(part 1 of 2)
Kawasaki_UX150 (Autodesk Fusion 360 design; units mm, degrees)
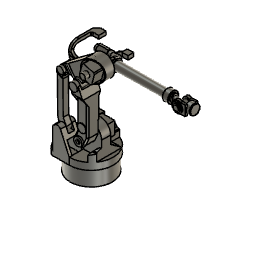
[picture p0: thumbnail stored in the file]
sketch "Esquisse1" plane through (0, 0, 0) normal (0, 0, 1) x axis (1, 0, 0)
sketch "Esquisse2" plane through (0, 0, 0) normal (0, 1, 0) x axis (1, 0, 0)
  line L1 (0, -3220) -> (0, 0)
  line L2 (335, -3220) -> (0, -3220)
  line L3 (2531, -3220) -> (335, -3220)
  line L4 (-1080, 0) -> (0, 0)
  point P1 (0, 0)
  point P2 (0, 0)
  point P6 (0, 0)
  point P3 (0, -3220)
  point P4 (335, -3220)
  point P5 (2531, -3220)
  point P7 (-1080, 0)
  coincident P1 P2
  perpendicular L1 L2
  perpendicular L1 L3
  coincident P1 P6
  dimension "d6" distance P2 P3 = 3220
  dimension "d7" distance P3 P4 = 335
  dimension "d8" distance P4 P5 = 2196
  dimension "d10" distance P6 P7 = 1080
canvas "Zone de dessin1"
sketch "Esquisse3" plane through (0, 0, 0) normal (0, 1, 0) x axis (1, 0, 0)
  line L1 (535, 0) -> (0, 0)
  line L2 (535, -700) -> (535, 0)
  line L3 (0, -700) -> (535, -700)
  line L4 (0, 0) -> (0, -700)
  line L5 (0, -3220) -> (0, 0)
  line L6 (335, -3220) -> (0, -3220)
  line L7 (335, -1870) -> (335, -3220)
  line L8 (335, -1600) -> (335, -1870)
  line L9 (135, -1600) -> (335, -1600)
  line L10 (135, -700) -> (135, -1600)
  line L11 (335, -3425) -> (335, -3220)
  line L12 (335, -3020) -> (335, -3220)
  line L13 (400, 0) -> (0, 0)
  line L14 (400, -400) -> (400, 0)
  line L15 (0, -400) -> (400, -400)
  line L16 (0, 0) -> (0, -400)
  line L17 (380, 0) -> (0, 0)
  line L18 (380, -275) -> (380, 0)
  line L19 (0, -275) -> (380, -275)
  line L20 (0, 0) -> (0, -275)
  line L21 (400, -275) -> (380, -275)
  line L22 (327.5, -400) -> (327.5, -700)
  line L23 (-215, -400) -> (0, -400)
  line L24 (-215, -735) -> (-215, -400)
  line L25 (-157.7529, -760.0802) -> (0, -400)
  line L26 (-465, -400) -> (0, -400)
  line L27 (-300, -400) -> (-465, -400)
  line L28 (-300, -750) -> (-300, -400)
  line L29 (-252.0768, -785.3146) -> (-300, -750)
  line L30 (-465, -400) -> (-300, -750)
  line L31 (-215, -1635) -> (-215, -735)
  line L32 (-215, -875) -> (-215, -735)
  line L33 (-215, -1475) -> (-215, -1635)
  line L34 (-159.3785, -1612.5) -> (-215, -1475)
  line L35 (-157.7529, -760.0802) -> (-215, -875)
  line L36 (-315, -1475) -> (-215, -1475)
  line L37 (-315, -850) -> (-315, -1475)
  line L38 (-274.8333, -716.9384) -> (-315, -850)
  line L39 (-315, -1520) -> (-315, -1475)
  line L40 (-272.1202, -1653.3654) -> (-315, -1520)
  line L41 (-159.3785, -1612.5) -> (135, -1600)
  line L42 (200, -1679) -> (335, -1679)
  line L43 (200, -1637.4166) -> (200, -1679)
  line L44 (223.3067, -2024.9374) -> (-250.0869, -1683.6714)
  circle C1 centre (335, -1870) radius 191
  circle C2 centre (335, -3220) radius 100
  circle C3 centre (135, -700) radius 192.5
  circle C4 centre (-215, -735) radius 62.5
  circle C5 centre (-215, -1635) radius 60
  circle C6 centre (135, -1600) radius 75
  point P1 (0, 0)
  point P2 (0, 0)
  point P6 (0, 0)
  point P7 (0, 0)
  point P13 (135, -700)
  point P10 (335, -1870)
  point P14 (335, -1870)
  point P9 (335, -3220)
  point P15 (335, -3220)
  point P16 (335, -3220)
  point P18 (335, -3020)
  point P19 (135, -700)
  point P23 (0, 0)
  point P27 (400, -275)
  point P28 (327.5, -700)
  point P29 (327.5, -400)
  point P31 (-215, -735)
  point P32 (-215, -735)
  point P33 (-157.7529, -760.0802)
  point P35 (-300, -400)
  point P37 (-252.0768, -785.3146)
  point P38 (-215, -1635)
  point P39 (-215, -1635)
  point P40 (-215, -875)
  point P41 (-215, -1475)
  point P42 (-159.3785, -1612.5)
  point P45 (-274.8333, -716.9384)
  point P47 (-272.1202, -1653.3654)
  point P12 (135, -1600)
  point P48 (135, -1600)
  point P49 (335, -1679)
  point P51 (200, -1637.4166)
  point P52 (-250.0869, -1683.6714)
  point P53 (223.3067, -2024.9374)
  point P3 (535, 0)
  point P8 (0, -3220)
  point P11 (335, -1600)
  point P17 (335, -3425)
  point P20 (400, 0)
  point P22 (0, -400)
  point P24 (380, 0)
  point P30 (-215, -400)
  point P34 (-465, -400)
  point P43 (-315, -1475)
  coincident P1 P2
  horizontal L1
  perpendicular L1 L2
  perpendicular L2 L3
  coincident P1 P6
  perpendicular L1 L4
  coincident P1 P7
  perpendicular L1 L5
  perpendicular L4 L6
  perpendicular L6 L7
  perpendicular L6 L8
  perpendicular L8 L9
  coincident L3 P13
  perpendicular L3 L10
  coincident P10 P14
  coincident P9 P15
  coincident P15 P16
  perpendicular L6 L11
  coincident L7 P18
  coincident P13 P19
  horizontal L13
  vertical L14
  horizontal L15
  vertical L16
  horizontal L17
  vertical L18
  horizontal L19
  vertical L20
  coincident P1 P23
  coincident L14 P27
  perpendicular L14 L21
  coincident C3 P28
  coincident L3 P28
  coincident L15 P29
  tangent C3 L22
  perpendicular L5 L23
  perpendicular L23 L24
  coincident P31 P32
  coincident C4 P33
  tangent C4 L25
  perpendicular L24 L26
  coincident L26 P35
  perpendicular L24 L27
  perpendicular L26 L28
  coincident C4 P37
  tangent C4 L29
  parallel L24 L31
  coincident P38 P39
  coincident L31 P40
  coincident L31 P41
  coincident C5 P42
  tangent C5 L34
  perpendicular L33 L36
  perpendicular L36 L37
  coincident C4 P45
  tangent C4 L38
  perpendicular L36 L39
  coincident C5 P47
  tangent C5 L40
  coincident P12 P48
  coincident C1 P49
  coincident L8 P49
  tangent C1 L42
  coincident C6 P51
  perpendicular L9 L43
  coincident C5 P52
  tangent C5 L44
  coincident C1 P53
  tangent C1 L44
  dimension "d11" distance P2 P3 = 535
  dimension "d12" distance P7 P8 = 3220
  dimension "d13" distance P8 P9 = 335
  dimension "d14" distance P9 P10 = 1350
  dimension "d15" distance P10 P11 = 270
  dimension "d16" distance P11 P12 = 200
  dimension "d17" diameter C1 = 382 (= "( 191 * 2 ) * 1 mm")
  dimension "d18" diameter C2 = 200
  dimension "d19" distance P16 P17 = 205
  dimension "d20" distance P9 P18 = 200
  dimension "d21" diameter C3 = 385
  dimension "d22" distance P6 P20 = 400
  dimension "d23" distance P6 P22 = 400
  dimension "d24" distance P23 P24 = 380
  dimension "d28" distance P22 P30 = 215
  dimension "d29" distance P30 P31 = 335
  dimension "d30" diameter C4 = 125
  dimension "d31" distance P22 P34 = 465
  dimension "d101" distance P31 P38 = 900
  dimension "d102" diameter C5 = 120
  dimension "d103" distance P41 P43 = 100
  dimension "d118" diameter C6 = 150
revolve "Révolution1" sketch "Esquisse3" AlongAngle 360
sketch "Esquisse4" plane through (0, 0, 0) normal (1, 0, 0) x axis (0, 1, 0)
  line L1 (0, 3425) -> (0, 0)
  point P1 (0, 0)
  point P2 (0, 0)
  point P3 (0, 3425)
  coincident P1 P2
  vertical L1
  dimension "d26" distance P2 P3 = 3425 (= "700 mm + 900 mm + 270 mm + 1350 mm + 205 mm")
revolve "Révolution3" sketch "Esquisse3" AlongAngle 360
canvas "Zone de dessin2"
revolve "Révolution2" sketch "Esquisse3" AlongAngle 360
extrude "Extrusion1" add sketch "Esquisse3" profile of L23 L24 C4 L25 L26 L27 L28 L29 L30 against normal blind 400
extrude "Extrusion2" cut of existing geometry blind -300
sketch "Esquisse5" plane through (0, 0, 0) normal (1, 0, 0) x axis (0, 1, 0)
  line L1 (0, 700) -> (0, 0)
  line L2 (25, 700) -> (0, 700)
  line L3 (25, 885) -> (25, 700)
  line L4 (-140, 885) -> (25, 885)
  line L5 (-140, 400) -> (-140, 885)
  line L6 (0, 400) -> (-140, 400)
  line L7 (25, 885) -> (-140, 885)
  line L8 (25, 400) -> (25, 885)
  line L9 (-140, 400) -> (25, 400)
  line L10 (-140, 885) -> (-140, 400)
  point P1 (0, 0)
  point P2 (0, 0)
  point P8 (0, 400)
  point P4 (25, 700)
  point P5 (25, 885)
  point P6 (-140, 885)
  coincident P1 P2
  vertical L1
  perpendicular L1 L2
  perpendicular L2 L3
  perpendicular L3 L4
  perpendicular L4 L5
  coincident L1 P8
  perpendicular L1 L6
  horizontal L7
  vertical L8
  horizontal L9
  vertical L10
  dimension "d37" distance P4 P5 = 185
  dimension "d38" distance P5 P6 = 165
extrude "Extrusion3" new body sketch "Esquisse3" profile of L3 L4 L5 L10 C3 along normal blind 25
extrude "Extrusion4" new body of existing geometry blind 140
sketch "Esquisse6" plane through (0, -140, 0) normal (0, -1, 0) x axis (1, 0, 0)
  circle C1 centre (135, 700) radius 192.5
  circle C2 centre (135, 700) radius 75
  concentric C1 C2
extrude "Extrusion5" new body sketch "Esquisse6" profile of C2 along normal blind 25
extrude "Extrusion6" add of existing geometry blind 125
combine "Combiner1"
sketch "Esquisse7" plane through (0, 0, 0) normal (0, 1, 0) x axis (1, 0, 0)
  line L1 (85, -1200) -> (0, -1200)
  line L2 (85, -1544.0983) -> (85, -1200)
  line L3 (285, -1200) -> (85, -1200)
  line L4 (285, -1450) -> (285, -1200)
  line L5 (203.3578, -1630.8578) -> (285, -1450)
  line L6 (285, -800) -> (285, -1200)
  line L7 (227.3077, -661.5385) -> (285, -800)
  line L8 (85, -830) -> (85, -1200)
  line L9 (44.2579, -742.0223) -> (85, -830)
  circle C1 centre (135, -1600) radius 75
  circle C2 centre (135, -700) radius 100
  point P5 (85, -1544.0983)
  point P9 (203.3578, -1630.8578)
  point P11 (227.3077, -661.5385)
  point P13 (44.2579, -742.0223)
  point P3 (0, -1200)
  point P4 (85, -1200)
  point P7 (285, -1200)
  point P12 (85, -830)
  horizontal L1
  coincident C1 P5
  perpendicular L1 L2
  perpendicular L2 L3
  perpendicular L3 L4
  coincident C1 P9
  tangent C1 L5
  perpendicular L3 L6
  coincident C2 P11
  tangent C2 L7
  perpendicular L3 L8
  coincident C2 P13
  tangent C2 L9
  dimension "d47" distance P3 P4 = 85
  dimension "d48" diameter C2 = 200
  dimension "d49" distance P4 P7 = 200
  dimension "d50" distance P4 P12 = 370
extrude "Extrusion7" new body sketch "Esquisse7" profile of C1 L2 C2 L3 L4 L5 L6 L7 L8 L9 against normal blind 500
sketch "Esquisse8" plane through (0, 0, 0) normal (1, 0, 0) x axis (0, 1, 0)
  line L1 (0, 700) -> (0, 0)
  line L2 (-250, 700) -> (0, 700)
  line L3 (-250, 1600) -> (-250, 700)
  line L4 (-100, 1600) -> (-250, 1600)
  line L5 (-250, 1600) -> (-100, 1600)
  line L6 (-465, 1600) -> (-250, 1600)
  line L7 (-465, 1525) -> (-465, 1600)
  line L8 (-440, 1525) -> (-465, 1525)
  line L9 (-440, 1465) -> (-440, 1525)
  line L10 (-465, 1675) -> (-465, 1600)
  line L11 (-400, 1675) -> (-465, 1675)
  line L12 (-400, 1525) -> (-400, 1675)
  line L13 (-150, 1525) -> (-400, 1525)
  line L14 (-150, 1680) -> (-150, 1525)
  line L15 (-100, 1680) -> (-150, 1680)
  line L16 (-100, 1525) -> (-100, 1680)
  line L17 (-115, 1525) -> (-100, 1525)
  line L18 (-115, 1460) -> (-115, 1525)
  line L19 (-150, 1460) -> (-115, 1460)
  line L20 (-150, 1010) -> (-150, 1460)
  line L21 (-160, 1010) -> (-150, 1010)
  line L22 (-160, 700) -> (-160, 1010)
  line L23 (-150, 1375) -> (-115, 1460)
  line L24 (-350, 700) -> (-250, 700)
  line L25 (-350, 1325) -> (-350, 700)
  line L26 (-440, 1465) -> (-350, 1325)
  line L27 (-350, 700) -> (-160, 700)
  line L28 (-350, 450) -> (-350, 700)
  line L29 (-160, 450) -> (-350, 450)
  line L30 (-160, 700) -> (-160, 450)
  point P1 (0, 0)
  point P2 (0, 0)
  point P23 (-160, 700)
  point P24 (-150, 1375)
  point P5 (-250, 1600)
  point P7 (-465, 1600)
  point P11 (-465, 1675)
  point P20 (-150, 1460)
  point P21 (-150, 1010)
  point P22 (-160, 1010)
  coincident P1 P2
  vertical L1
  perpendicular L1 L2
  perpendicular L2 L3
  perpendicular L3 L4
  perpendicular L3 L6
  perpendicular L6 L7
  perpendicular L7 L8
  perpendicular L8 L9
  perpendicular L6 L10
  perpendicular L7 L11
  perpendicular L6 L12
  perpendicular L12 L13
  perpendicular L13 L14
  perpendicular L14 L15
  perpendicular L4 L16
  perpendicular L16 L17
  perpendicular L17 L18
  perpendicular L18 L19
  perpendicular L19 L20
  perpendicular L20 L21
  coincident L2 P23
  perpendicular L2 L22
  coincident L20 P24
  perpendicular L3 L24
  perpendicular L24 L25
  horizontal L27
  vertical L28
  horizontal L29
  vertical L30
  dimension "d53" distance P5 P7 = 215
  dimension "d54" distance P7 P11 = 75
  dimension "d55" distance P20 P21 = 450
  dimension "d56" distance P21 P22 = 10
extrude "Extrusion8" new body sketch "Esquisse8" profile of L2 L3 L4 L5 L6 L7 L8 L9 L10 L11 L12 L13 L14 L15 L16 L17 L18 L19 L20 L21 L22 L23 L24 L25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 along normal blind 300 and against normal blind 300
combine "Combiner2"
sketch "Esquisse9" plane through (0, -100, 0) normal (0, 1, 0) x axis (-1, 0, 0)
  line L1 (-251.1438, 1525) -> (-203.3578, 1630.8578)
  line L2 (-85, 1525) -> (-251.1438, 1525)
  line L3 (-85, 1544.0983) -> (-85, 1525)
  arc A1 centre (-135, 1600) radius 75 clockwise from (-203.3578, 1630.8578) to (-85, 1544.0983)
  circle C1 centre (-135, 1600) radius 75
  concentric A1 C1
extrude "Extrusion9" cut sketch "Esquisse9" profile of L1 L2 L3 C1 against normal blind 15
sketch "Esquisse10" plane through (0, -465, 0) normal (0, -1, 0) x axis (1, 0, 0)
  line L1 (203.3578, 1630.8578) -> (251.1438, 1525)
  line L2 (85, 1525) -> (85, 1544.0983)
  line L3 (251.1438, 1525) -> (85, 1525)
  arc A1 centre (135, 1600) radius 75 clockwise from (85, 1544.0983) to (203.3578, 1630.8578)
  circle C1 centre (135, 1600) radius 75
  concentric A1 C1
extrude "Extrusion10" cut sketch "Esquisse10" profile of L1 L2 L3 C1 against normal blind 25
sketch "Esquisse11" plane through (0, -150, 0) normal (0, -1, 0) x axis (1, 0, 0)
  line L1 (85, 1525) -> (85, 1544.0983)
  line L2 (251.1438, 1525) -> (85, 1525)
  line L3 (203.3578, 1630.8578) -> (251.1438, 1525)
  line L4 (217.2876, 1600) -> (210, 1600)
  arc A1 centre (135, 1600) radius 75 clockwise from (85, 1544.0983) to (203.3578, 1630.8578)
  circle C1 centre (135, 1600) radius 75
  point P8 (210, 1600)
  point P9 (217.2876, 1600)
  concentric A1 C1
  coincident C1 P8
  coincident L3 P9
  horizontal L4
extrude "Extrusion11" add sketch "Esquisse11" profile of L1 L2 L3 C1 L4 along normal blind 250
fillet "Congé1" radius 15
fillet "Congé2" radius 5
sketch "Esquisse12" plane through (0, -400, 0) normal (0, -1, 0) x axis (1, 0, 0)
  line L1 (-300, 750) -> (-252.0768, 785.3146)
  line L2 (-465, 400) -> (-300, 750)
  line L3 (-465, 275) -> (-465, 400)
  line L4 (0, 275) -> (-465, 275)
  line L5 (0, 400) -> (0, 275)
  line L6 (-157.7529, 760.0802) -> (0, 400)
  line L7 (-300, 350) -> (-300, 750)
  line L8 (-400, 350) -> (-300, 350)
  line L9 (-400, 275) -> (-400, 350)
  arc A1 centre (-215, 735) radius 62.5 clockwise from (-252.0768, 785.3146) to (-157.7529, 760.0802)
  point P5 (-300, 750)
  point P10 (-300, 750)
  point P13 (-400, 275)
  coincident P5 P10
  vertical L7
  perpendicular L7 L8
  coincident L4 P13
  perpendicular L4 L9
extrude "Extrusion12" new body of existing geometry blind 170
extrude "Extrusion13" cut of existing geometry blind -110
extrude "Extrusion14" cut sketch "Esquisse12" profile of L2 L3 L4 L7 L8 L9 against normal blind 100
extrude "Extrusion15" add of existing geometry blind 110
sketch "Esquisse13" plane through (0, 0, 0) normal (1, 0, 0) x axis (0, 1, 0)
  line L1 (-190, 784.775) -> (-131.0189, 784.775)
  line L2 (-190, 660) -> (-190, 784.775)
  line L3 (-300, 660) -> (-190, 660)
  line L4 (-300, 810) -> (-300, 660)
  line L5 (-190, 810) -> (-300, 810)
  line L6 (-190, 784.775) -> (-190, 810)
  line L7 (-350, 340) -> (-170, 340)
  line L8 (-350, 600) -> (-350, 340)
  line L9 (-170, 600) -> (-350, 600)
  line L10 (-170, 340) -> (-170, 600)
  horizontal L1
  perpendicular L1 L2
  perpendicular L2 L3
  perpendicular L3 L4
  perpendicular L4 L5
  perpendicular L1 L6
  horizontal L7
  vertical L8
  horizontal L9
  vertical L10
extrude "Extrusion16" cut of existing geometry blind -100
extrude "Extrusion17" cut sketch "Esquisse13" profile of L2 L3 L4 L5 L6 L7 L8 L9 L10 against normal blind 700
extrude "Extrusion18" cut of existing geometry blind -10
sketch "Esquisse14" plane through (0, -350, 0) normal (0, -1, 0) x axis (1, 0, 0)
  line L1 (285, 1325) -> (285, 800)
  line L2 (85, 1325) -> (285, 1325)
  line L3 (85, 830) -> (85, 1325)
  line L4 (44.2579, 742.0223) -> (85, 830)
  line L5 (285, 800) -> (227.3077, 661.5385)
  line L6 (185, 1349.9999) -> (185, 1350)
  line L7 (110, 1350) -> (110, 1349.9999)
  line L8 (260, 1349.9999) -> (260, 1349.9998)
  line L9 (185, 925) -> (185, 1349.9999)
  line L10 (260, 925) -> (260, 1349.9998)
  line L11 (110, 925) -> (110, 1350)
  arc A1 centre (135, 700) radius 100 clockwise from (227.3077, 661.5385) to (44.2579, 742.0223)
  circle C1 centre (185, 1349.9999) radius 75
  circle C2 centre (185, 1350) radius 75
  circle C3 centre (135, 700) radius 75
  circle C4 centre (185, 925) radius 75
  circle C5 centre (135, 700) radius 37.5
  point P10 (185, 1349.9999)
  point P11 (185, 1349.9999)
  point P9 (185, 1350)
  point P12 (185, 1350)
  point P14 (110, 1349.9999)
  point P15 (110, 1350)
  point P16 (260, 1349.9998)
  point P17 (260, 1349.9999)
  point P18 (185, 1349.9999)
  point P19 (185, 925)
  point P20 (185, 925)
  point P21 (260, 925)
  point P22 (110, 925)
  coincident P10 P11
  coincident P9 P12
  concentric A1 C3
  coincident C1 P14
  tangent C1 L7
  coincident C2 P15
  tangent C2 L7
  perpendicular L2 L7
  coincident C1 P16
  tangent C1 L8
  coincident C2 P17
  tangent C2 L8
  coincident P11 P18
  perpendicular L2 L9
  coincident P19 P20
  coincident C4 P21
  tangent C4 L10
  vertical L10
  coincident C4 P22
  tangent C4 L11
  parallel L10 L11
  concentric C3 C5
  dimension "d89" diameter C1 = 150
  dimension "d90" diameter C2 = 150
  dimension "d91" diameter C3 = 150
  dimension "d92" diameter C4 = 150
  dimension "d95" diameter C5 = 75
extrude "Extrusion19" cut sketch "Esquisse14" profile of L2 C1 C2 L7 L8 L9 C4 L10 L11 along normal blind 250
extrude "Extrusion20" new body sketch "Esquisse14" profile of C3 C5 along normal blind 30
extrude "Extrusion21" new body sketch "Esquisse14" profile of C4 along normal blind 10
chamfer "Chanfrein" distance 25
extrude "Extrusion22" new body sketch "Esquisse3" profile of L24 C4 L29 L31 C5 L32 L33 L34 L35 L36 L37 L38 L39 L40 against normal blind 850
sketch "Esquisse15" plane through (0, 0, 0) normal (1, 0, 0) x axis (0, 1, 0)
  line L1 (0, 735) -> (0, 0)
  line L2 (-250, 735) -> (0, 735)
  line L3 (-300, 735) -> (-250, 735)
  line L4 (-200, 735) -> (-300, 735)
  line L5 (-200, 670) -> (-200, 735)
  line L6 (-300, 670) -> (-200, 670)
  line L7 (-300, 735) -> (-300, 670)
  line L8 (-300, 1500) -> (-300, 735)
  line L9 (-335, 1520) -> (-300, 1500)
  line L10 (-335, 1700) -> (-335, 1520)
  line L11 (-350, 1700) -> (-335, 1700)
  line L12 (-350, 1570) -> (-350, 1700)
  line L13 (-335, 1570) -> (-350, 1570)
  line L14 (-150, 1700) -> (-335, 1700)
  line L15 (-150, 1570) -> (-150, 1700)
  line L16 (-150, 1510) -> (-150, 1570)
  line L17 (-200, 1510) -> (-150, 1510)
  line L18 (-200, 735) -> (-200, 1510)
  line L19 (-150, 1500) -> (-150, 1510)
  line L20 (-200, 1500) -> (-150, 1500)
  line L21 (-335, 1500) -> (-335, 1520)
  line L22 (-300, 1500) -> (-335, 1500)
  line L23 (-160, 1500) -> (-160, 1700)
  line L24 (-160, 1570) -> (-150, 1570)
  line L25 (-300, 1700) -> (-200, 1700)
  line L26 (-300, 1550) -> (-300, 1700)
  line L27 (-200, 1550) -> (-300, 1550)
  line L28 (-200, 1700) -> (-200, 1550)
  point P1 (0, 0)
  point P2 (0, 0)
  point P6 (-200, 735)
  point P14 (-335, 1570)
  point P20 (-200, 1500)
  point P22 (-160, 1700)
  point P23 (-160, 1500)
  point P24 (-160, 1570)
  point P25 (-200, 1700)
  coincident P1 P2
  vertical L1
  perpendicular L1 L2
  perpendicular L1 L3
  coincident L2 P6
  perpendicular L4 L5
  perpendicular L5 L6
  perpendicular L3 L7
  perpendicular L3 L8
  perpendicular L3 L10
  perpendicular L8 L11
  perpendicular L11 L12
  coincident L10 P14
  perpendicular L10 L13
  perpendicular L10 L14
  perpendicular L14 L15
  perpendicular L14 L16
  perpendicular L16 L17
  perpendicular L4 L18
  perpendicular L17 L19
  coincident L18 P20
  perpendicular L18 L20
  perpendicular L20 L21
  perpendicular L8 L22
  coincident L14 P22
  coincident L20 P23
  perpendicular L20 L23
  coincident L23 P24
  perpendicular L23 L24
  horizontal L25
  vertical L26
  horizontal L27
  vertical L28
  coincident L14 P25
extrude "Extrusion23" new body sketch "Esquisse15" profile of L2 L3 L4 L5 L6 L7 L8 L9 L10 L11 L12 L13 L14 L15 L17 L18 L21 L22 L23 L24 L26 L27 L28 against normal blind 700
combine "Combiner3"
sketch "Esquisse16" plane through (-728.4123, 0, 234.2002) normal (-0.952, 0, 0.3061) x axis (0, -1, 0)
  line L1 (335, 1403.1469) -> (335, 1350.6261)
  line L2 (350, 1403.1469) -> (335, 1403.1469)
  line L3 (350, 1490.7153) -> (350, 1403.1469)
  line L4 (300, 1490.7153) -> (350, 1490.7153)
  line L5 (300, 1382.1386) -> (300, 1490.7153)
  line L6 (200, 1382.1386) -> (300, 1382.1386)
  line L7 (200, 1490.7153) -> (200, 1382.1386)
  line L8 (150, 1490.7153) -> (200, 1490.7153)
  line L9 (150, 1403.1469) -> (150, 1490.7153)
  line L10 (160, 1403.1469) -> (150, 1403.1469)
  line L11 (160, 1350.6261) -> (160, 1403.1469)
  line L12 (335, 1350.6261) -> (160, 1350.6261)
  line L13 (300, 1403.1469) -> (335, 1403.1469)
  line L14 (335, 1325) -> (335, 1403.1469)
  line L15 (300, 1325) -> (335, 1325)
  line L16 (300, 1403.1469) -> (300, 1325)
  line L17 (200, 1403.1469) -> (160, 1403.1469)
  line L18 (200, 1325) -> (200, 1403.1469)
  line L19 (160, 1325) -> (200, 1325)
  line L20 (160, 1403.1469) -> (160, 1325)
  line L21 (300, 1403.1469) -> (200, 1403.1469)
  line L22 (200, 1490.7153) -> (200, 1403.1469)
  line L23 (200, 1490.7153) -> (300, 1490.7153)
  line L24 (300, 1350.6261) -> (335, 1403.1469)
  line L25 (200, 1350.6261) -> (160, 1403.1469)
  point P3 (335, 1403.1469)
  point P14 (335, 1403.1469)
  point P15 (300, 1403.1469)
  point P16 (335, 1403.1469)
  point P12 (160, 1403.1469)
  point P19 (160, 1403.1469)
  point P20 (200, 1403.1469)
  point P23 (160, 1403.1469)
  point P9 (200, 1490.7153)
  point P24 (200, 1490.7153)
  point P6 (300, 1490.7153)
  point P25 (300, 1490.7153)
  point P26 (200, 1490.7153)
  point P27 (300, 1350.6261)
  point P28 (160, 1403.1469)
  point P29 (200, 1350.6261)
  coincident P3 P14
  coincident L5 P15
  perpendicular L5 L13
  coincident P3 P16
  perpendicular L13 L14
  perpendicular L14 L15
  perpendicular L13 L16
  coincident P12 P19
  coincident L7 P20
  perpendicular L7 L17
  perpendicular L15 L18
  perpendicular L18 L19
  coincident P12 P23
  perpendicular L17 L20
  coincident P9 P24
  coincident P6 P25
  coincident P9 P26
  coincident L12 P27
  coincident L16 P27
  coincident P12 P28
  coincident L12 P29
  coincident L18 P29
extrude "Extrusion24" cut sketch "Esquisse16" profile of L1 L5 L7 L11 L12 L13 L14 L15 L16 L17 L18 L19 L20 against normal blind 240
extrude "Extrusion25" cut sketch "Esquisse16" profile of L5 L7 L21 L22 L23 against normal blind 280
extrude "Extrusion26" add sketch "Esquisse16" profile of L5 L6 L7 L16 L18 L21 against normal blind 90
sketch "Esquisse17" plane through (0, -350, 0) normal (0, -1, 0) x axis (1, 0, 0)
  line L1 (-159.3785, 1612.5) -> (-176.5706, 1570)
  line L2 (-298.9239, 1570) -> (-272.1202, 1653.3654)
  line L3 (-176.5706, 1570) -> (-298.9239, 1570)
  arc A1 centre (-215, 1635) radius 60 clockwise from (-272.1202, 1653.3654) to (-159.3785, 1612.5)
  circle C1 centre (-215, 1635) radius 60
  point P4 (-272.1202, 1653.3654)
  concentric A1 C1
  coincident P4 C1
extrude "Extrusion27" cut sketch "Esquisse17" profile of L1 L2 L3 C1 against normal blind 15
sketch "Esquisse18" plane through (0, -150, 0) normal (0, 1, 0) x axis (-1, 0, 0)
  line L1 (176.5706, 1570) -> (159.3785, 1612.5)
  line L2 (298.9239, 1570) -> (176.5706, 1570)
  line L3 (272.1202, 1653.3654) -> (298.9239, 1570)
  arc A1 centre (215, 1635) radius 60 clockwise from (159.3785, 1612.5) to (272.1202, 1653.3654)
  circle C1 centre (215, 1635) radius 60
  concentric A1 C1
extrude "Extrusion28" cut sketch "Esquisse18" profile of L1 L2 L3 C1 against normal blind 10
sketch "Esquisse19" plane through (-697.5262, 0, 282.1633) normal (0.927, 0, -0.375) x axis (0, 1, 0)
  line L1 (-300, 1351.663) -> (-200, 1351.663)
  line L2 (-300, 1286.7366) -> (-300, 1351.663)
  line L3 (-200, 1286.7366) -> (-300, 1286.7366)
  line L4 (-200, 1351.663) -> (-200, 1286.7366)
  line L5 (-335, 1351.663) -> (-300, 1351.663)
  line L6 (-300, 1286.7366) -> (-335, 1351.663)
  line L7 (-200, 1351.663) -> (-200, 1286.7366)
  line L8 (-160, 1351.663) -> (-200, 1351.663)
  line L9 (-200, 1286.7366) -> (-160, 1351.663)
  point P3 (-300, 1351.663)
  point P6 (-300, 1351.663)
  point P4 (-300, 1286.7366)
  point P8 (-300, 1286.7366)
  point P5 (-200, 1286.7366)
  point P9 (-200, 1286.7366)
  point P2 (-200, 1351.663)
  point P10 (-200, 1351.663)
  point P11 (-200, 1351.663)
  point P13 (-200, 1286.7366)
  coincident P3 P6
  perpendicular L2 L5
  coincident P4 P8
  coincident P5 P9
  coincident P2 P10
  coincident P2 P11
  perpendicular L4 L8
  coincident P5 P13
loft "Lissage1" sketch "Esquisse16" + "Esquisse19"
loft "Lissage2" sketch "Esquisse19" + "Esquisse16"
extrude "Extrusion29" new body sketch "Esquisse3" profile of L7 L8 C1 against normal blind 300
extrude "Extrusion30" cut of existing geometry blind -100
sketch "Esquisse20" plane through (0, -300, 0) normal (0, -1, 0) x axis (1, 0, 0)
  line L1 (255, 2010) -> (475, 1950)
  line L2 (195, 1790) -> (255, 2010)
  line L3 (415, 1730) -> (195, 1790)
  line L4 (475, 1950) -> (415, 1730)
  circle C1 centre (335, 1870) radius 191
  circle C2 centre (335, 1870) radius 175
  circle C3 centre (335, 1870) radius 150
  circle C4 centre (335, 1870) radius 50
  point P3 (335, 1870)
  point P9 (335, 1870)
  concentric C1 C2
  concentric C1 C3
  coincident P3 P9
  concentric C2 C4
  dimension "d123" diameter C2 = 350
  dimension "d124" diameter C3 = 300
extrude "Extrusion31" add sketch "Esquisse20" profile of C3 L1 L2 L3 L4 along normal blind 110
extrude "Extrusion32" new body sketch "Esquisse20" profile of C4 along normal blind 190
extrude "Extrusion33" add sketch "Esquisse20" profile of C1 C2 along normal blind 50
sketch "Esquisse21" plane through (0, 0, 0) normal (1, 0, 0) x axis (0, 1, 0)
  line L1 (0, 1870) -> (0, 0)
  line L2 (-500, 1870) -> (0, 1870)
  line L3 (-344.8683, 1959.605) -> (-300, 1825)
  line L4 (-500, 2060) -> (-500, 1870)
  line L5 (-100, 2060) -> (-310, 2060)
  line L6 (-100, 1680) -> (-100, 2060)
  line L7 (-500, 1675) -> (-100, 1680)
  line L8 (-500, 1870) -> (-500, 1675)
  line L9 (-300, 1677.5) -> (-300, 1825)
  line L10 (-350, 1991.2278) -> (-350, 2020)
  line L11 (-325, 2060) -> (-310, 2060)
  line L12 (-500, 2060) -> (-325, 2060)
  arc A1 centre (-310, 2020) radius 40 clockwise from (-350, 2020) to (-310, 2060)
  arc A2 centre (-250, 1991.2278) radius 100 clockwise from (-344.8683, 1959.605) to (-350, 1991.2278)
  point P1 (0, 0)
  point P2 (0, 0)
  point P10 (-300, 1677.5)
  point P6 (-500, 2060)
  point P3 (0, 1870)
  point P4 (-500, 1870)
  coincident P1 P2
  vertical L1
  perpendicular L1 L2
  perpendicular L2 L4
  perpendicular L4 L5
  perpendicular L5 L6
  perpendicular L2 L8
  midpoint L7 P10
  vertical L9
  perpendicular L5 L10
  coincident P6 L5
  tangent L5 A1
  tangent L10 A1
  tangent L3 A2
  tangent L10 A2
  tangent A1 L11
  perpendicular L4 L12
  dimension "d131" distance P2 P3 = 1870 (= "700 mm + 900 mm + 270 mm")
  dimension "d133" distance P4 P6 = 190
  dimension "d134" radius A1 = 40
  dimension "d135" radius A2 = 100
combine "Combiner4"
combine "Combiner5"
extrude "Extrusion34" new body sketch "Esquisse3" profile of C5 against normal blind 300
extrude "Extrusion35" cut sketch "Esquisse3" profile of C5 against normal blind 200
extrude "Extrusion36" new body sketch "Esquisse3" profile of L9 L10 L41 C6 against normal blind 400
extrude "Extrusion37" cut of existing geometry blind -150
extrude "Extrusion38" new body sketch "Esquisse3" profile of L5 C1 C5 L41 C6 L42 L43 L44 against normal blind 350
extrude "Extrusion39" cut of existing geometry blind -200
sketch "Esquisse22" plane through (-884.2043, 0, 1226.5408) normal (-0.5848, 0, 0.8112) x axis (0, -1, 0)
  line L1 (200, 781.7118) -> (200, 1365.2904)
  line L2 (350, 781.7118) -> (200, 781.7118)
  line L3 (350, 1365.2904) -> (350, 781.7118)
  line L4 (200, 1365.2904) -> (350, 1365.2904)
  line L5 (300, 971.7118) -> (350, 971.7118)
  line L6 (300, 901.7118) -> (300, 971.7118)
  line L7 (350, 971.7118) -> (300, 901.7118)
  line L8 (300, 781.7118) -> (300, 901.7118)
  point P6 (350, 971.7118)
  point P9 (300, 781.7118)
  coincident L3 P6
  perpendicular L3 L5
  perpendicular L5 L6
  coincident L2 P9
  perpendicular L2 L8
extrude "Extrusion40" cut sketch "Esquisse22" profile of L2 L3 L7 L8 against normal blind 350
fillet "Congé3" radius 125
sketch "Esquisse23" plane through (-884.2043, 0, 1226.5408) normal (-0.5848, 0, 0.8112) x axis (0, -1, 0)
  line L1 (350, 1365.2904) -> (350, 1011.7699)
  line L2 (200, 1365.2904) -> (350, 1365.2904)
  line L3 (200, 781.7118) -> (200, 1365.2904)
  line L4 (300, 781.7118) -> (200, 781.7118)
  line L5 (300, 861.6537) -> (300, 781.7118)
  line L6 (326.7167, 939.1151) -> (323.2833, 934.3084)
  line L7 (175, 1365.2904) -> (200, 1365.2904)
  line L8 (175, 965.2904) -> (175, 1365.2904)
  line L9 (200, 965.2904) -> (175, 965.2904)
  line L10 (175, 781.7118) -> (175, 965.2904)
  line L11 (200, 781.7118) -> (175, 781.7118)
  arc A1 centre (225, 1011.7699) radius 125 clockwise from (350, 1011.7699) to (326.7167, 939.1151)
  arc A2 centre (425, 861.6537) radius 125 clockwise from (300, 861.6537) to (323.2833, 934.3084)
  point P6 (200, 1365.2904)
  point P12 (200, 1365.2904)
  point P15 (200, 965.2904)
  point P7 (200, 781.7118)
  point P17 (200, 781.7118)
  point P13 (175, 1365.2904)
  point P14 (175, 965.2904)
  coincident P6 P12
  perpendicular L3 L7
  perpendicular L2 L8
  coincident L3 P15
  perpendicular L3 L9
  perpendicular L4 L10
  coincident P7 P17
  perpendicular L3 L11
  dimension "d152" distance P12 P13 = 25
  dimension "d153" distance P13 P14 = 400
extrude "Extrusion41" add of existing geometry blind 25
extrude "Extrusion42" cut sketch "Esquisse23" profile of L3 L9 L10 L11 against normal blind 375
fillet "Congé4" radius 162.5
fillet "Congé5" radius 15
fillet "Congé6" radius 20
canvas "Zone de dessin3"
sketch "Esquisse24" plane through (0, 0, 400) normal (0, 0, 1) x axis (-1, 0, 0)
  line L1 (0, 170) -> (0, 130)
  line L2 (0, 350) -> (0, 170)
  line L3 (0, 400) -> (0, 350)
  line L4 (0, 130) -> (378.2856, 130)
  line L5 (25, 0) -> (0, 0)
  line L6 (475, 0) -> (25, 0)
  line L7 (475, -200) -> (475, 0)
  line L8 (475, 0) -> (475, -200)
  line L9 (325, -400) -> (0, -400)
  line L10 (325, 400) -> (0, 400)
  line L11 (400, 200) -> (475, 200)
  line L12 (465, 70.7643) -> (465, 200)
  line L13 (475, 70.7643) -> (465, 70.7643)
  line L14 (465, 222.2611) -> (465, 200)
  line L15 (465, -222.2611) -> (465, 222.2611)
  line L16 (400, 170) -> (400, 200)
  line L17 (465, 170) -> (400, 170)
  line L18 (378.2856, 130) -> (400, 170)
  line L19 (487.8225, 437.9256) -> (271.7466, 437.9256)
  line L20 (487.8225, 166.2956) -> (487.8225, 437.9256)
  line L21 (400, 325) -> (400, 200)
  arc A1 centre (0, 0) radius 400 clockwise from (378.2856, 130) to (0, 400)
  circle C1 centre (0, 0) radius 515.3882
  point P7 (0, 0)
  point P8 (0, 0)
  point P13 (0, -400)
  point P5 (0, 400)
  point P15 (0, 400)
  point P14 (325, -400)
  point P11 (475, -200)
  point P16 (325, 400)
  point P22 (465, 222.2611)
  point P23 (465, -222.2611)
  point P25 (465, 170)
  point P6 (378.2856, 130)
  point P26 (378.2856, 130)
  point P27 (271.7466, 437.9256)
  point P29 (487.8225, 166.2956)
  point P30 (400, 325)
  point P12 (475, 200)
  point P19 (465, 200)
  coincident P7 P8
  parallel L4 L5
  parallel L4 L6
  perpendicular L6 L7
  coincident A1 P13
  tangent A1 L9
  horizontal L9
  coincident P5 P15
  tangent A1 L10
  coincident P14 C1
  coincident P11 C1
  coincident P16 C1
  perpendicular L2 L11
  vertical L12
  horizontal L13
  coincident C1 P22
  perpendicular L11 L14
  coincident C1 P23
  parallel L7 L15
  perpendicular L11 L16
  coincident L12 P25
  coincident P6 P26
  coincident C1 P27
  horizontal L19
  coincident C1 P29
  perpendicular L19 L20
  coincident C1 P30
  perpendicular L11 L21
  dimension "d164" distance P12 P19 = 10
  dimension "d165" angle L16 L17 = 90
extrude "Extrusion43" add sketch "Esquisse24" profile of A1 L6 L9 C1 L12 L15 L17 L18 against normal blind 125
extrude "Extrusion44" cut sketch "Esquisse24" profile of C1 L19 L20 against normal blind 125
extrude "Extrusion45" add sketch "Esquisse24" profile of C1 L11 L14 L15 L21 against normal blind 125
extrude "Extrusion46" cut of existing geometry blind -60
sketch "Esquisse25" plane through (0, 25, 0) normal (0, 1, 0) x axis (-1, 0, 0)
  line L1 (-327.5, 400) -> (-327.5, 700)
  line L2 (57.5, 400) -> (57.5, 700)
  line L3 (-327.5, 400) -> (57.5, 400)
  circle C1 centre (-135, 700) radius 192.5
  point P3 (-327.5, 700)
  point P5 (57.5, 700)
  coincident C1 P3
  tangent C1 L1
  vertical L1
  coincident C1 P5
  tangent C1 L2
  vertical L2
  perpendicular L1 L3
extrude "Extrusion47" add sketch "Esquisse25" against normal blind 165
sketch "Esquisse26" plane through (0, 0, 400) normal (0, 0, 1) x axis (-1, 0, 0)
  line L1 (57.5, -25) -> (57.5, 130)
  line L2 (-327.5, -25) -> (57.5, -25)
  line L3 (-327.5, 140) -> (-327.5, -25)
  line L4 (0, 140) -> (-327.5, 140)
  line L5 (0, 170) -> (0, 140)
  line L6 (0, 350) -> (0, 170)
  line L7 (0, 400) -> (0, 350)
  line L8 (325, -400) -> (0, -400)
  line L9 (465, 130) -> (465, -222.2611)
  line L10 (57.5, 130) -> (465, 130)
  line L11 (415.1485, -106.16) -> (365.5689, -243.1294)
  line L12 (126.733, -147.2878) -> (212.6213, -264.9396)
  line L13 (50, -320) -> (310, -320)
  line L14 (50, -25) -> (50, -320)
  line L15 (0, -320) -> (50, -320)
  line L16 (0, -25) -> (0, -320)
  line L17 (0, -25) -> (0, -320)
  line L18 (0, -25) -> (57.5, -25)
  line L19 (0, -25) -> (0, -320)
  line L20 (0, -25) -> (50, -25)
  line L21 (-140, -374.6999) -> (-140, -320)
  line L22 (0, -320) -> (-140, -320)
  line L23 (310, -380) -> (310, -320)
  line L24 (325, -380) -> (310, -380)
  line L25 (325, -400) -> (325, -380)
  line L26 (50, -400) -> (50, -320)
  line L27 (0, -400) -> (0, -320)
  line L28 (-140, -25) -> (-140, -320)
  arc A1 centre (0, 0) radius 400 clockwise from (0, -400) to (0, 400)
  arc A2 centre (0, 0) radius 515.3882 clockwise from (465, -222.2611) to (325, -400)
  circle C1 centre (260, -50) radius 165
  circle C2 centre (283.2932, -213.3476) radius 87.5
  point P16 (283.2932, -213.3476)
  point P17 (365.5689, -243.1294)
  point P18 (415.1485, -106.16)
  point P19 (212.6213, -264.9396)
  point P20 (126.733, -147.2878)
  point P23 (50, -25)
  point P25 (0, -25)
  point P3 (57.5, -25)
  point P26 (57.5, -25)
  point P28 (-140, -374.6999)
  point P12 (325, -400)
  point P31 (325, -400)
  point P32 (50, -400)
  point P10 (0, -400)
  point P33 (0, -400)
  point P34 (-140, -25)
  coincident C1 P16
  coincident C2 P17
  tangent C2 L11
  coincident C1 P18
  tangent C1 L11
  coincident C2 P19
  tangent C2 L12
  coincident C1 P20
  tangent C1 L12
  horizontal L13
  coincident L2 P23
  perpendicular L2 L14
  perpendicular L14 L15
  coincident L2 P25
  perpendicular L2 L16
  coincident P3 P26
  coincident A1 P28
  perpendicular L15 L21
  perpendicular L17 L22
  perpendicular L13 L23
  perpendicular L23 L24
  coincident P12 P31
  perpendicular L8 L25
  coincident L8 P32
  perpendicular L8 L26
  coincident P10 P33
  perpendicular L8 L27
  coincident L2 P34
  perpendicular L2 L28
  dimension "d176" diameter C1 = 330
  dimension "d177" diameter C2 = 175
extrude "Extrusion48" add sketch "Esquisse26" profile of L2 L8 L13 L14 L15 L16 L17 L18 L19 L20 L23 L24 L25 L26 L27 along normal blind 150
extrude "Extrusion49" add sketch "Esquisse26" profile of C1 C2 L11 L12 along normal blind 50
extrude "Extrusion50" add sketch "Esquisse26" profile of L2 A1 L16 L17 L19 L21 L22 L27 L28 along normal blind 150
sketch "Esquisse27" plane through (0, 400, 0) normal (0, 1, 0) x axis (-1, 0, 0)
  line L1 (0, 275) -> (0, 550)
  line L2 (325, 275) -> (0, 275)
  line L3 (325, 400) -> (325, 275)
  line L4 (325, 550) -> (325, 400)
  line L5 (0, 550) -> (325, 550)
  line L6 (-75, 500) -> (0, 550)
  line L7 (-125, 500) -> (-75, 500)
  line L8 (-155.9493, 479.3672) -> (-125, 500)
  line L9 (-155.9493, 400) -> (-155.9493, 479.3672)
  line L10 (0, 400) -> (-155.9493, 400)
  line L11 (-155.9493, 550) -> (-155.9493, 479.3672)
  line L12 (0, 550) -> (-155.9493, 550)
  point P2 (0, 550)
  point P7 (0, 550)
  point P12 (0, 400)
  point P14 (0, 550)
  coincident P2 P7
  perpendicular L1 L7
  parallel L6 L8
  perpendicular L5 L9
  coincident L1 P12
  perpendicular L1 L10
  parallel L9 L11
  coincident P2 P14
  perpendicular L1 L12
extrude "Extrusion51" cut sketch "Esquisse27" profile of L6 L7 L8 L11 L12 against normal blind 375
sketch "Esquisse28" plane through (0, 25, 0) normal (0, 1, 0) x axis (-1, 0, 0)
  line L1 (50, 550) -> (0, 550)
  line L2 (50, 400) -> (50, 550)
  line L3 (57.5, 400) -> (50, 400)
  line L4 (57.5, 700) -> (57.5, 400)
  line L5 (-327.5, 400) -> (-327.5, 700)
  line L6 (-140, 400) -> (-327.5, 400)
  line L7 (-140, 490) -> (-140, 400)
  line L8 (-125, 500) -> (-140, 490)
  line L9 (-75, 500) -> (-125, 500)
  line L10 (0, 550) -> (-75, 500)
  arc A1 centre (-135, 700) radius 192.5 clockwise from (-327.5, 700) to (57.5, 700)
  circle C1 centre (-135, 700) radius 167.5
  concentric A1 C1
  dimension "d187" diameter C1 = 335
extrude "Extrusion52" cut sketch "Esquisse28" profile of C1 against normal blind 100
sketch "Esquisse29" plane through (0, -75, 0) normal (0, 1, 0) x axis (-1, 0, 0)
  line L1 (-250, 585) -> (-20, 585)
  line L2 (-250, 815) -> (-250, 585)
  line L3 (-20, 815) -> (-250, 815)
  line L4 (-20, 585) -> (-20, 815)
  line L5 (-250, 815) -> (-20, 585)
  line L6 (-20, 815) -> (-250, 585)
  circle C1 centre (-135, 700) radius 167.5
  circle C2 centre (-135, 700) radius 50
  point P7 (-135, 700)
  point P2 (-135, 700)
  point P8 (-135, 700)
  point P5 (-250, 815)
  point P6 (-20, 815)
  point P4 (-250, 585)
  horizontal L1
  perpendicular L1 L2
  parallel L1 L3
  parallel L2 L4
  coincident L5 P7
  coincident L6 P7
  coincident P2 P7
  coincident P7 P8
  dimension "d190" distance P5 P6 = 230
  dimension "d191" distance P4 P5 = 230
  dimension "d196" diameter C2 = 100
extrude "Extrusion53" add sketch "Esquisse29" profile of L1 L2 L3 L4 along normal blind 250
extrude "Extrusion54" add of existing geometry blind 5
extrude "Extrusion55" add sketch "Esquisse29" profile of C2 along normal blind 300
sketch "Esquisse30" plane through (0, 0, 450) normal (0, 0, 1) x axis (-1, 0, 0)
  line L1 (415.1485, -106.16) -> (365.5689, -243.1294)
  line L2 (212.6213, -264.9396) -> (126.733, -147.2878)
  line L3 (50, -290) -> (280, -290)
  line L4 (50, -60) -> (50, -290)
  line L5 (280, -60) -> (50, -60)
  line L6 (280, -290) -> (280, -60)
  line L7 (50, -60) -> (280, -290)
  line L8 (280, -60) -> (50, -290)
  arc A1 centre (260, -50) radius 165 clockwise from (126.733, -147.2878) to (415.1485, -106.16)
  arc A2 centre (283.2932, -213.3476) radius 87.5 clockwise from (365.5689, -243.1294) to (212.6213, -264.9396)
  circle C1 centre (165, -175) radius 50
  point P12 (165, -175)
  point P13 (165, -175)
  point P10 (50, -60)
  point P11 (280, -60)
  point P9 (50, -290)
  horizontal L3
  perpendicular L3 L4
  parallel L3 L5
  parallel L4 L6
  coincident L7 P12
  coincident L8 P12
  coincident P12 P13
  dimension "d199" distance P10 P11 = 230
  dimension "d200" distance P9 P10 = 230
  dimension "d201" diameter C1 = 100
extrude "Extrusion56" add sketch "Esquisse30" profile of A1 L2 A2 L3 L4 L5 L6 C1 along normal blind 200
extrude "Extrusion57" add sketch "Esquisse30" profile of A1 L2 C1 along normal blind 250
sketch "Esquisse31" plane through (0, 0, 400) normal (0, 0, 1) x axis (-1, 0, 0)
  line L1 (-140, -25) -> (-140, -374.6999)
  line L2 (-327.5, -25) -> (-140, -25)
  line L3 (-327.5, 140) -> (-327.5, -25)
  line L4 (0, 140) -> (-327.5, 140)
  line L5 (0, 170) -> (0, 140)
  line L6 (0, 350) -> (0, 170)
  line L7 (0, 400) -> (0, 350)
  line L8 (-327.5, -210) -> (-327.5, -25)
  line L9 (-140, -210) -> (-327.5, -210)
  line L10 (-307.5, -25) -> (-327.5, -25)
  line L11 (-307.5, -210) -> (-307.5, -25)
  arc A1 centre (0, 0) radius 400 clockwise from (-140, -374.6999) to (0, 400)
  point P4 (-327.5, -25)
  point P11 (-327.5, -25)
  point P13 (-140, -210)
  point P15 (-307.5, -210)
  point P12 (-327.5, -210)
  point P14 (-307.5, -25)
  coincident P4 P11
  perpendicular L2 L8
  coincident L1 P13
  perpendicular L1 L9
  perpendicular L8 L10
  coincident L9 P15
  perpendicular L9 L11
  dimension "d206" distance P11 P12 = 185
  dimension "d207" distance P11 P14 = 20
sketch "Esquisse32" plane through (0, 25, 0) normal (0, 1, 0) x axis (-1, 0, 0)
  line L1 (50, 550) -> (0, 550)
  line L2 (50, 400) -> (50, 550)
  line L3 (57.5, 400) -> (50, 400)
  line L4 (57.5, 700) -> (57.5, 400)
  line L5 (-327.5, 400) -> (-327.5, 700)
  line L6 (-140, 400) -> (-327.5, 400)
  line L7 (-140, 490) -> (-140, 400)
  line L8 (-125, 500) -> (-140, 490)
  line L9 (-75, 500) -> (-125, 500)
  line L10 (0, 550) -> (-75, 500)
  line L11 (-307.5, 400) -> (-327.5, 400)
  line L12 (-307.5, 550) -> (-307.5, 400)
  line L13 (-327.5, 550) -> (-307.5, 550)
  line L14 (-327.5, 400) -> (-327.5, 550)
  circle C1 centre (-135, 700) radius 167.5
  arc A1 centre (-135, 700) radius 192.5 clockwise from (-327.5, 700) to (57.5, 700)
  point P9 (-327.5, 400)
  point P14 (-327.5, 400)
  point P15 (-307.5, 400)
  horizontal L11
  vertical L12
  horizontal L13
  vertical L14
  coincident P9 P14
  dimension "d208" distance P14 P15 = 20
extrude "Extrusion58" add sketch "Esquisse31" profile of L1 L2 L8 L9 L10 L11 along normal blind 20
sketch "Esquisse33" plane through (0, 0, 420) normal (0, 0, 1) x axis (-1, 0, 0)
  line L1 (-140, -210) -> (-327.5, -210)
  line L2 (-140, -25) -> (-140, -210)
  line L3 (-327.5, -25) -> (-140, -25)
  line L4 (-327.5, -210) -> (-327.5, -25)
  line L5 (-307.5, -210) -> (-327.5, -210)
  line L6 (-307.5, -25) -> (-307.5, -210)
  line L7 (-327.5, -25) -> (-307.5, -25)
  line L8 (-327.5, -210) -> (-327.5, -25)
  point P8 (-307.5, -25)
  point P2 (-327.5, -210)
  point P6 (-327.5, -210)
  point P7 (-307.5, -210)
  horizontal L5
  vertical L6
  horizontal L7
  vertical L8
  coincident L3 P8
  coincident P2 P6
  dimension "d211" distance P6 P7 = 20
loft "Lissage3" sketch "Esquisse32" + "Esquisse33"
sketch "Esquisse34" plane through (0, 0, 400) normal (0, 0, 1) x axis (-1, 0, 0)
  line L1 (-327.5, -210) -> (-140, -210)
  line L2 (-327.5, 140) -> (-327.5, -210)
  line L3 (0, 140) -> (-327.5, 140)
  line L4 (0, 170) -> (0, 140)
  line L5 (0, 350) -> (0, 170)
  line L6 (0, 400) -> (0, 350)
  line L7 (-140, -210) -> (-140, -374.6999)
  line L8 (-327.5, 229.6601) -> (-327.5, 140)
  line L9 (-163.75, 140) -> (-327.5, 140)
  line L10 (-163.75, 364.9465) -> (-163.75, 140)
  arc A1 centre (0, 0) radius 400 clockwise from (-140, -374.6999) to (0, 400)
  point P4 (-327.5, 140)
  point P11 (-327.5, 140)
  point P12 (-327.5, 229.6601)
  point P13 (-163.75, 140)
  point P14 (-163.75, 364.9465)
  coincident P4 P11
  coincident A1 P12
  perpendicular L3 L8
  midpoint L3 P13
  coincident A1 P14
  perpendicular L9 L10
sketch "Esquisse35" plane through (0, -140, 0) normal (0, -1, 0) x axis (1, 0, 0)
  line L1 (-57.5, 531.2471) -> (-57.5, 700)
  line L2 (0, 400) -> (-57.5, 531.2471)
  line L3 (327.5, 400) -> (0, 400)
  line L4 (327.5, 700) -> (327.5, 400)
  line L5 (250, 525) -> (250, 400)
  line L6 (280, 540) -> (250, 525)
  line L7 (280, 560) -> (280, 540)
  line L8 (313.6414, 576.8207) -> (280, 560)
  line L9 (327.5, 576.8207) -> (313.6414, 576.8207)
  arc A1 centre (135, 700) radius 192.5 clockwise from (-57.5, 700) to (327.5, 700)
  circle C1 centre (135, 700) radius 193.5628
  point P9 (250, 400)
  point P14 (327.5, 576.8207)
  point P10 (250, 525)
  concentric A1 C1
  coincident L3 P9
  perpendicular L3 L5
  perpendicular L3 L7
  parallel L6 L8
  coincident L4 P14
  perpendicular L4 L9
  dimension "d212" distance P9 P10 = 125
extrude "Extrusion59" new body sketch "Esquisse34" profile of L3 A1 L8 L9 L10 along normal blind 225
extrude "Extrusion60" new body sketch "Esquisse35" profile of L3 L4 L5 L6 L7 L8 L9 along normal blind 525
sketch "Esquisse36" plane through (327.5, 0, 0) normal (1, 0, 0) x axis (0, 1, 0)
  line L1 (-140, 576.8207) -> (-140, 400)
  line L2 (-665, 576.8207) -> (-140, 576.8207)
  line L3 (-665, 400) -> (-665, 576.8207)
  line L4 (-140, 400) -> (-665, 400)
  line L5 (-225, 550) -> (-140, 576.8207)
  line L6 (-225, 400) -> (-225, 550)
  arc A1 centre (-234.2926, 349.6705) radius 175.5755 clockwise from (-402.5, 400) to (-225, 525)
  point P3 (-140, 576.8207)
  point P6 (-140, 576.8207)
  point P10 (-402.5, 400)
  point P9 (-225, 525)
  coincident P3 P6
  perpendicular L2 L6
  midpoint L4 P10
  coincident L6 P9
extrude "Extrusion61" new body sketch "Esquisse36" profile of L1 L4 L5 L6 A1 against normal blind 275
combine "Combiner6"
combine "Combiner7"
combine "Combiner8"
extrude "Extrusion62" add of existing geometry blind 100
extrude "Extrusion63" add of existing geometry blind 100
extrude "Extrusion64" cut sketch "Esquisse30" profile of A1 L2 A2 L3 L4 L5 L6 C1 along normal blind 100
extrude "Extrusion65" add of existing geometry blind 30
extrude "Extrusion66" add of existing geometry blind 20
sketch "Esquisse37" plane through (0, 25, 0) normal (0, 1, 0) x axis (-1, 0, 0)
  line L1 (-75, 500) -> (-75, 520)
  line L2 (0, 550) -> (-75, 500)
  line L3 (0, 580) -> (0, 550)
  line L4 (50, 580) -> (0, 580)
  line L5 (50, 400) -> (50, 580)
  line L6 (57.5, 400) -> (50, 400)
  line L7 (57.5, 700) -> (57.5, 400)
  line L8 (-327.5, 550) -> (-327.5, 700)
  line L9 (-307.5, 550) -> (-327.5, 550)
  line L10 (-307.5, 420) -> (-307.5, 550)
  line L11 (-140, 420) -> (-307.5, 420)
  line L12 (-140, 490) -> (-140, 420)
  line L13 (-125, 500) -> (-140, 490)
  line L14 (-125, 520) -> (-125, 500)
  line L15 (-75, 520) -> (-125, 520)
  line L16 (0, 580) -> (-75, 520)
  line L17 (-140, 510) -> (-125, 520)
  line L18 (-140, 490) -> (-140, 510)
  arc A1 centre (-135, 700) radius 192.5 clockwise from (-327.5, 700) to (57.5, 700)
  circle C1 centre (-135, 700) radius 167.5
  point P2 (-75, 520)
  point P19 (-75, 520)
  point P5 (0, 580)
  point P20 (0, 580)
  point P18 (-125, 520)
  point P21 (-125, 520)
  point P16 (-140, 490)
  point P23 (-140, 490)
  coincident P2 P19
  coincident P5 P20
  coincident P18 P21
  parallel L2 L17
  coincident P16 P23
  parallel L12 L18
extrude "Extrusion67" add sketch "Esquisse37" profile of L1 L2 L3 L13 L14 L16 L17 L18 along normal blind 390
sketch "Esquisse38" plane through (0, 0, 275) normal (0, 0, -1) x axis (1, 0, 0)
  line L1 (-465, -222.2611) -> (-465, 222.2611)
  line L2 (0, -400) -> (-325, -400)
  line L3 (-325, 400) -> (0, 400)
  line L4 (-40, -485.3997) -> (211.0376, -485.3997)
  line L5 (-40, -330) -> (-40, -485.3997)
  line L6 (211.0376, -330) -> (-40, -330)
  line L7 (211.0376, -485.3997) -> (211.0376, -330)
  arc A1 centre (0, 0) radius 515.3882 clockwise from (-465, 222.2611) to (-325, 400)
  arc A2 centre (0, 0) radius 515.3882 clockwise from (-325, -400) to (-465, -222.2611)
  arc A3 centre (0, 0) radius 400 clockwise from (0, 400) to (0, -400)
  circle C1 centre (0, 0) radius 380
  horizontal L4
  vertical L5
  horizontal L6
  vertical L7
extrude "Extrusion68" cut sketch "Esquisse38" profile of L2 A3 L4 L5 L7 against normal blind 305
work_plane "Plan de construction1" AlongDistance 335
sketch "Esquisse39" plane through (335, 0, 0) normal (1, 0, 0) x axis (0, 1, 0)
  line L1 (0, 1870) -> (0, 0)
  line L2 (0, 3220) -> (0, 1870)
  line L3 (-100, 1870) -> (0, 1870)
  line L4 (-100, 1880) -> (-100, 1870)
  line L5 (0, 1880) -> (-100, 1880)
  line L6 (0, 1870) -> (0, 1880)
  point P1 (0, 0)
  point P2 (0, 0)
  point P3 (0, 1870)
  point P4 (0, 3220)
  coincident P1 P2
  vertical L1
  parallel L1 L2
  horizontal L3
  vertical L4
  horizontal L5
  vertical L6
  dimension "d234" distance P2 P3 = 1870 (= "700 mm + 900 mm + 270 mm")
  dimension "d235" distance P3 P4 = 1350
revolve "Révolution4" sketch "Esquisse39" AlongAngle 360
extrude "Extrusion69" add of existing geometry blind 25
combine "Combiner9"
sketch "Esquisse40" plane through (0, 0, 0) normal (1, 0, 0) x axis (0, 1, 0)
  line L1 (330, 1980) -> (-100, 1980)
  line L2 (330, 1860) -> (330, 1980)
  line L3 (-100, 1860) -> (330, 1860)
  line L4 (-100, 1980) -> (-100, 1860)
  horizontal L1
  vertical L2
  horizontal L3
  vertical L4
extrude "Extrusion70" new body sketch "Esquisse40" along normal blind 650
sketch "Esquisse41" plane through (0, 0, 1980) normal (0, 0, 1) x axis (-1, 0, 0)
  line L1 (0, 100) -> (0, -330)
  line L2 (-650, 100) -> (0, 100)
  line L3 (-650, -330) -> (-650, 100)
  line L4 (0, -330) -> (-650, -330)
  line L5 (-335, 0) -> (0, 0)
  line L6 (-152.6777, -17.6777) -> (-281.967, -146.967)
  line L7 (-335, 200) -> (-152.6777, 17.6777)
  line L8 (-517.3223, 17.6777) -> (-335, 200)
  line L9 (-388.033, -146.967) -> (-517.3223, -17.6777)
  circle C1 centre (-335, 0) radius 200
  arc A1 centre (-335, -93.934) radius 75 clockwise from (-281.967, -146.967) to (-388.033, -146.967)
  arc A2 centre (-170.3553, 0) radius 25 clockwise from (-152.6777, 17.6777) to (-152.6777, -17.6777)
  arc A3 centre (-499.6447, 0) radius 25 clockwise from (-517.3223, -17.6777) to (-517.3223, 17.6777)
  point P1 (0, 0)
  point P6 (0, 0)
  point P7 (-335, 0)
  point P8 (-335, 0)
  point P10 (-335, 0)
  coincident P1 P6
  perpendicular L1 L5
  coincident P7 P8
  coincident P8 P10
  tangent L6 A1
  tangent L9 A1
  tangent L6 A2
  tangent L7 A2
  tangent L9 A3
  tangent L8 A3
  equal A2 A3
  dimension "d241" distance P6 P7 = 335
  dimension "d242" diameter C1 = 400
  dimension "d243" radius A1 = 75
  dimension "d244" radius A2 = 25
extrude "Extrusion71" new body sketch "Esquisse41" profile of L2 L6 L7 L8 L9 A1 A2 A3 against normal blind 200
combine "Combiner10"
remove_body "RemoveBody1"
